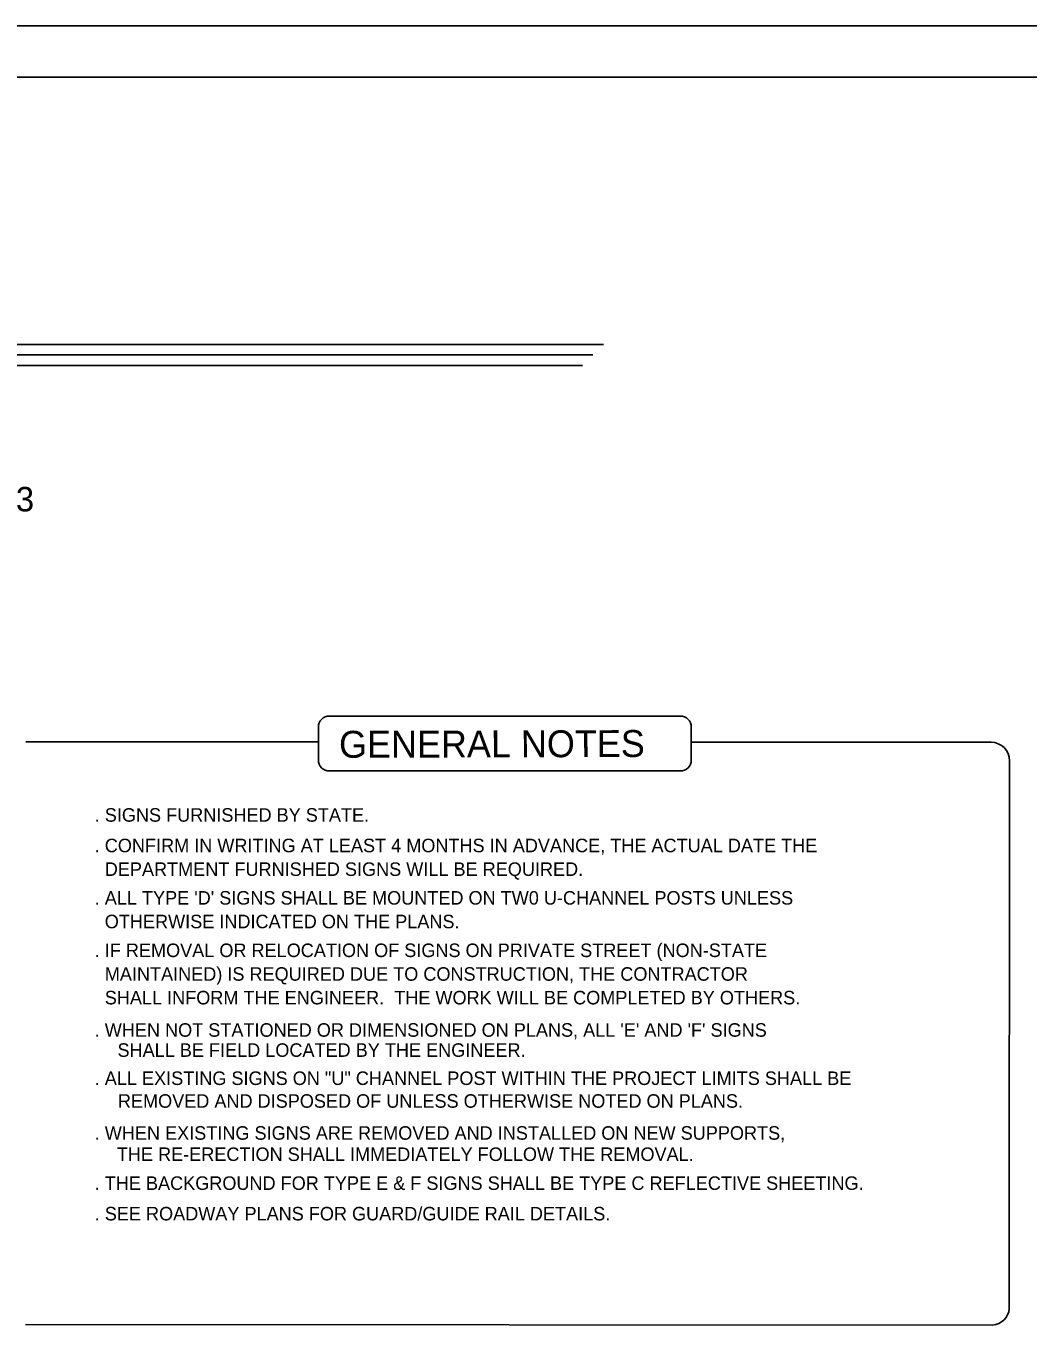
# Model space of a CAD drawing. Extents: x -2362 to 1945, y 0 to 1100.
# Drawn here: x 1039 to 1531, y 462 to 1100 of the extents above; entities that cross this region are included whole.
import ezdxf

# ---------------------------------------------------------------- set-up
doc = ezdxf.new("R2010")
doc.units = 0
for name, color, linetype in [('Default', 7, 'Continuous'), ('Exist Utilities Telephone Test Hole SUE LOS A CELL', 7, 'Continuous'), ('Sheet_Title_Block_Text', 7, 'Continuous'), ('z - Construction', 7, 'Continuous')]:
    doc.layers.add(name, color=color, linetype=linetype)

msp = doc.modelspace()

# ---------------------------------------------------------------- linework, layer by layer
at = {"layer": 'Exist Utilities Telephone Test Hole SUE LOS A CELL'}
msp.add_line((0, 1100), (1699.98, 1100), dxfattribs=at)
at = {"layer": 'z - Construction'}
for p, q in [((38.08, 1074.94), (1651.98, 1074.94)), ((417.2, 943.68), (1322.86, 943.68)), ((422.34, 938.54), (1317.72, 938.54)), ((427.48, 933.4), (1312.58, 933.4)), ((1182.93, 739.81), (1182.93, 755.83)), ((1365.96, 739.81), (1365.96, 755.83)), ((1039.46, 748.67), (1182.93, 748.6)), ((1365.97, 748.52), (1513.07, 748.45)), ((1521.99, 470.4), (1522.15, 739.36)), ((1039.29, 462.63), (1513.83, 462.41))]:
    msp.add_line(p, q, dxfattribs=at)
for points in [[(1188.38, 761.29), (1360.51, 761.29)], [(1188.38, 734.36), (1360.51, 734.36)]]:
    msp.add_lwpolyline(points, dxfattribs=at)
for centre, radius, start, end in [((1188.38, 755.83), 5.45, 90, 180), ((1360.51, 755.83), 5.45, 360, 90), ((1513.06, 739.36), 9.09, 359.97341, 89.97341), ((1188.38, 739.81), 5.45, 180, 270), ((1360.51, 739.81), 5.45, 270, 360), ((1513.37, 471.04), 8.64, 273.04586, 355.76805)]:
    msp.add_arc(centre, radius, start, end, dxfattribs=at)

# ---------------------------------------------------------------- texts
at = {"layer": 'Default'}
for s, p in [('. SIGNS FURNISHED BY STATE.', (1073.19, 709.44)), ('. CONFIRM IN WRITING AT LEAST 4 MONTHS IN ADVANCE, THE ACTUAL DATE THE', (1073.19, 694.46)), ('  DEPARTMENT FURNISHED SIGNS WILL BE REQUIRED.', (1073.19, 682.84)), (". ALL TYPE 'D' SIGNS SHALL BE MOUNTED ON TW0 U-CHANNEL POSTS UNLESS", (1073.19, 668.75)), ('  OTHERWISE INDICATED ON THE PLANS.', (1073.19, 657.14)), ('. IF REMOVAL OR RELOCATION OF SIGNS ON PRIVATE STREET (NON-STATE ', (1073.19, 643.01)), ('  MAINTAINED) IS REQUIRED DUE TO CONSTRUCTION, THE CONTRACTOR ', (1073.19, 631.39)), ('  SHALL INFORM THE ENGINEER.  THE WORK WILL BE COMPLETED BY OTHERS.', (1073.19, 619.78)), (". WHEN NOT STATIONED OR DIMENSIONED ON PLANS, ALL 'E' AND 'F' SIGNS ", (1073.19, 603.9)), ('SHALL BE FIELD LOCATED BY THE ENGINEER.', (1084.36, 594.04)), ('. ALL EXISTING SIGNS ON "U" CHANNEL POST WITHIN THE PROJECT LIMITS SHALL BE', (1073.19, 580.22)), ('REMOVED AND DISPOSED OF UNLESS OTHERWISE NOTED ON PLANS.', (1084.57, 569.05)), ('. WHEN EXISTING SIGNS ARE REMOVED AND INSTALLED ON NEW SUPPORTS, ', (1073.19, 553.35)), ('THE RE-ERECTION SHALL IMMEDIATELY FOLLOW THE REMOVAL.', (1084.05, 542.92)), ('. THE BACKGROUND FOR TYPE E & F SIGNS SHALL BE TYPE C REFLECTIVE SHEETING. ', (1073.19, 528.73)), ('. SEE ROADWAY PLANS FOR GUARD/GUIDE RAIL DETAILS.', (1073.19, 513.75))]:
    msp.add_text(s, height=6.6381, dxfattribs=at).set_placement(p)
at = {"layer": 'Sheet_Title_Block_Text'}
for s, height, rotation, p in [('LOCATION: REPLACE BRIDGE 700037 ON NC 53', 12, 0.12484, (675.13, 860.96)), ('GENERAL NOTES', 13.2, 0.15565, (1193.09, 740.81))]:
    msp.add_text(s, height=height, rotation=rotation, dxfattribs=at).set_placement(p)

doc.saveas('drawing.dxf')
